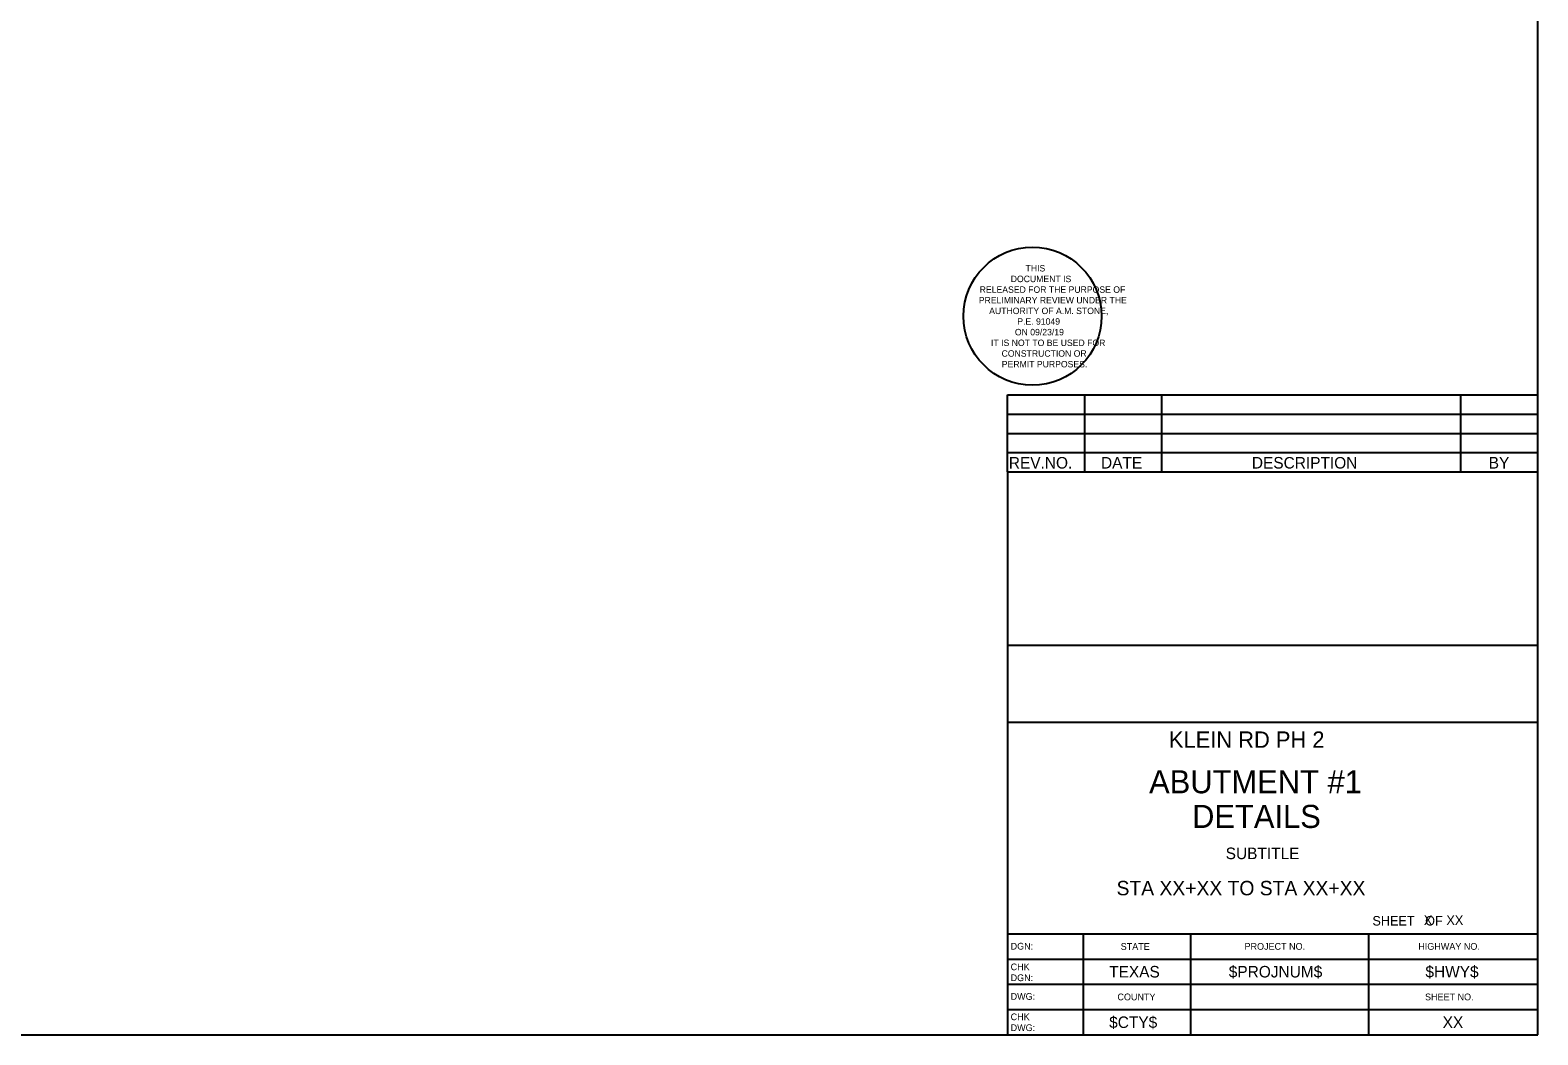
# Model space of a CAD drawing. Extents: x 970 to 1074, y 989 to 1045.
# Drawn here: x 1052.09 to 1067.76, y 1024.24 to 1034.69 of the extents above; entities that cross this region are included whole.
import ezdxf

# ---------------------------------------------------------------- set-up
doc = ezdxf.new("R2010")
doc.units = 0
for name, color, linetype in [('BORD_lines_major', 7, 'Continuous'), ('BORD_lines_minor', 7, 'Continuous'), ('BORD_text_large_1', 7, 'Continuous'), ('BORD_text_large_2', 7, 'Continuous'), ('BORD_text_SHEET', 7, 'Continuous'), ('BORD_text_small_1', 7, 'Continuous'), ('BORD_text_small_2', 7, 'Continuous'), ('BORD_text_small_3', 7, 'Continuous'), ('BORD_text_small_proj', 7, 'Continuous'), ('C-MS-ANNO-TTLB-STMP', 7, 'Continuous')]:
    doc.layers.add(name, color=color, linetype=linetype)

msp = doc.modelspace()

# ---------------------------------------------------------------- linework, layer by layer
at = {"layer": 'BORD_lines_major'}
for p, q in [((1067.759, 1024.245), (1067.759, 1045.127)), ((1036.673, 1024.245), (1067.759, 1024.245))]:
    msp.add_line(p, q, dxfattribs=at)
at = {"layer": 'BORD_lines_minor'}
for p, q in [((1062.248, 1030.895), (1067.759, 1030.895)), ((1062.248, 1030.095), (1062.248, 1030.895)), ((1063.048, 1030.895), (1063.048, 1030.095)), ((1063.848, 1030.895), (1063.848, 1030.095)), ((1066.959, 1030.095), (1066.959, 1030.895)), ((1062.248, 1030.695), (1067.759, 1030.695)), ((1062.248, 1030.495), (1067.759, 1030.495)), ((1062.248, 1030.295), (1067.759, 1030.295)), ((1062.248, 1030.095), (1067.759, 1030.095)), ((1062.248, 1030.095), (1062.248, 1028.295)), ((1062.248, 1028.295), (1067.759, 1028.295)), ((1062.248, 1028.295), (1062.248, 1024.245)), ((1062.248, 1027.495), (1067.759, 1027.495)), ((1062.248, 1025.295), (1067.759, 1025.295)), ((1063.035, 1025.295), (1063.035, 1024.245)), ((1064.148, 1025.295), (1064.148, 1024.245)), ((1065.998, 1025.295), (1065.998, 1024.245)), ((1062.248, 1025.032), (1067.759, 1025.032)), ((1062.248, 1024.77), (1067.759, 1024.77)), ((1062.248, 1024.507), (1067.759, 1024.507))]:
    msp.add_line(p, q, dxfattribs=at)
at = {"layer": 'C-MS-ANNO-TTLB-STMP'}
msp.add_circle((1062.507, 1031.713), 0.717, dxfattribs=at)

# ---------------------------------------------------------------- texts
at = {"layer": 'BORD_lines_minor'}
for s, p in [('REV.NO.', (1062.261, 1030.13)), ('DATE', (1063.219, 1030.13)), ('DESCRIPTION', (1064.787, 1030.13)), ('BY', (1067.249, 1030.13))]:
    msp.add_text(s, height=0.12, rotation=359.9834, dxfattribs=at).set_placement(p)
msp.add_text('KLEIN RD PH 2', height=0.17, dxfattribs=at).set_placement((1063.925, 1027.228))
at = {"layer": 'BORD_text_large_1'}
for s, p in [('ABUTMENT #1', (1063.719, 1026.755)), ('DETAILS', (1064.166, 1026.395))]:
    msp.add_text(s, height=0.24, dxfattribs=at).set_placement(p)
at = {"layer": 'BORD_text_large_2'}
msp.add_text('STA XX+XX TO STA XX+XX', height=0.15, dxfattribs=at).set_placement((1063.381, 1025.695))
at = {"layer": 'BORD_text_SHEET'}
msp.add_text('XX', height=0.12, dxfattribs=at).set_placement((1066.77, 1024.316))
at = {"layer": 'BORD_text_small_1'}
msp.add_text('SHEET   OF', height=0.0984, dxfattribs=at).set_placement((1066.04, 1025.381))
at = {"layer": 'BORD_text_small_2'}
msp.add_text('SUBTITLE', height=0.12, rotation=359.9834, dxfattribs=at).set_placement((1064.515, 1026.071))
at = {"layer": 'BORD_text_small_3'}
msp.add_text('X    XX', height=0.0984, dxfattribs=at).set_placement((1066.575, 1025.387))
at = {"layer": 'BORD_text_small_proj'}
for s, height, p in [('DGN:', 0.07, (1062.28, 1025.131)), ('STATE', 0.07, (1063.424, 1025.128)), ('PROJECT NO.', 0.07, (1064.711, 1025.129)), ('HIGHWAY NO.', 0.07, (1066.517, 1025.129)), ('CHK', 0.07, (1062.28, 1024.916)), ('DGN:', 0.07, (1062.28, 1024.803)), ('TEXAS', 0.12, (1063.304, 1024.841)), ('$HWY$', 0.12, (1066.591, 1024.841)), ('DWG:', 0.07, (1062.28, 1024.609)), ('COUNTY', 0.07, (1063.39, 1024.604)), ('SHEET NO.', 0.07, (1066.587, 1024.604)), ('CHK', 0.07, (1062.28, 1024.397)), ('DWG:', 0.07, (1062.28, 1024.284)), ('$CTY$', 0.12, (1063.304, 1024.316))]:
    msp.add_text(s, height=height, rotation=359.9834, dxfattribs=at).set_placement(p)
msp.add_text('$PROJNUM$', height=0.12, dxfattribs=at).set_placement((1064.547, 1024.841))
at = {"layer": 'C-MS-ANNO-TTLB-STMP'}
for s, height, p in [('THIS', 0.0672, (1062.435, 1032.178)), ('RELEASED FOR THE PURPOSE OF', 0.06723, (1061.958, 1031.956)), ('DOCUMENT IS', 0.06723, (1062.281, 1032.067)), ('PRELIMINARY REVIEW UNDER THE', 0.06723, (1061.949, 1031.846)), ('AUTHORITY OF A.M. STONE,', 0.06723, (1062.057, 1031.735)), ('ON 09/23/19', 0.06723, (1062.324, 1031.514)), ('P.E. 91049', 0.0672, (1062.349, 1031.625)), ('IT IS NOT TO BE USED FOR', 0.06723, (1062.076, 1031.403)), ('CONSTRUCTION OR', 0.06723, (1062.186, 1031.292)), ('PERMIT PURPOSES.', 0.06723, (1062.188, 1031.181))]:
    msp.add_text(s, height=height, rotation=360, dxfattribs=at).set_placement(p)

doc.saveas('drawing.dxf')
